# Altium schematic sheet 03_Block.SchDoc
size 459 x 350 mm
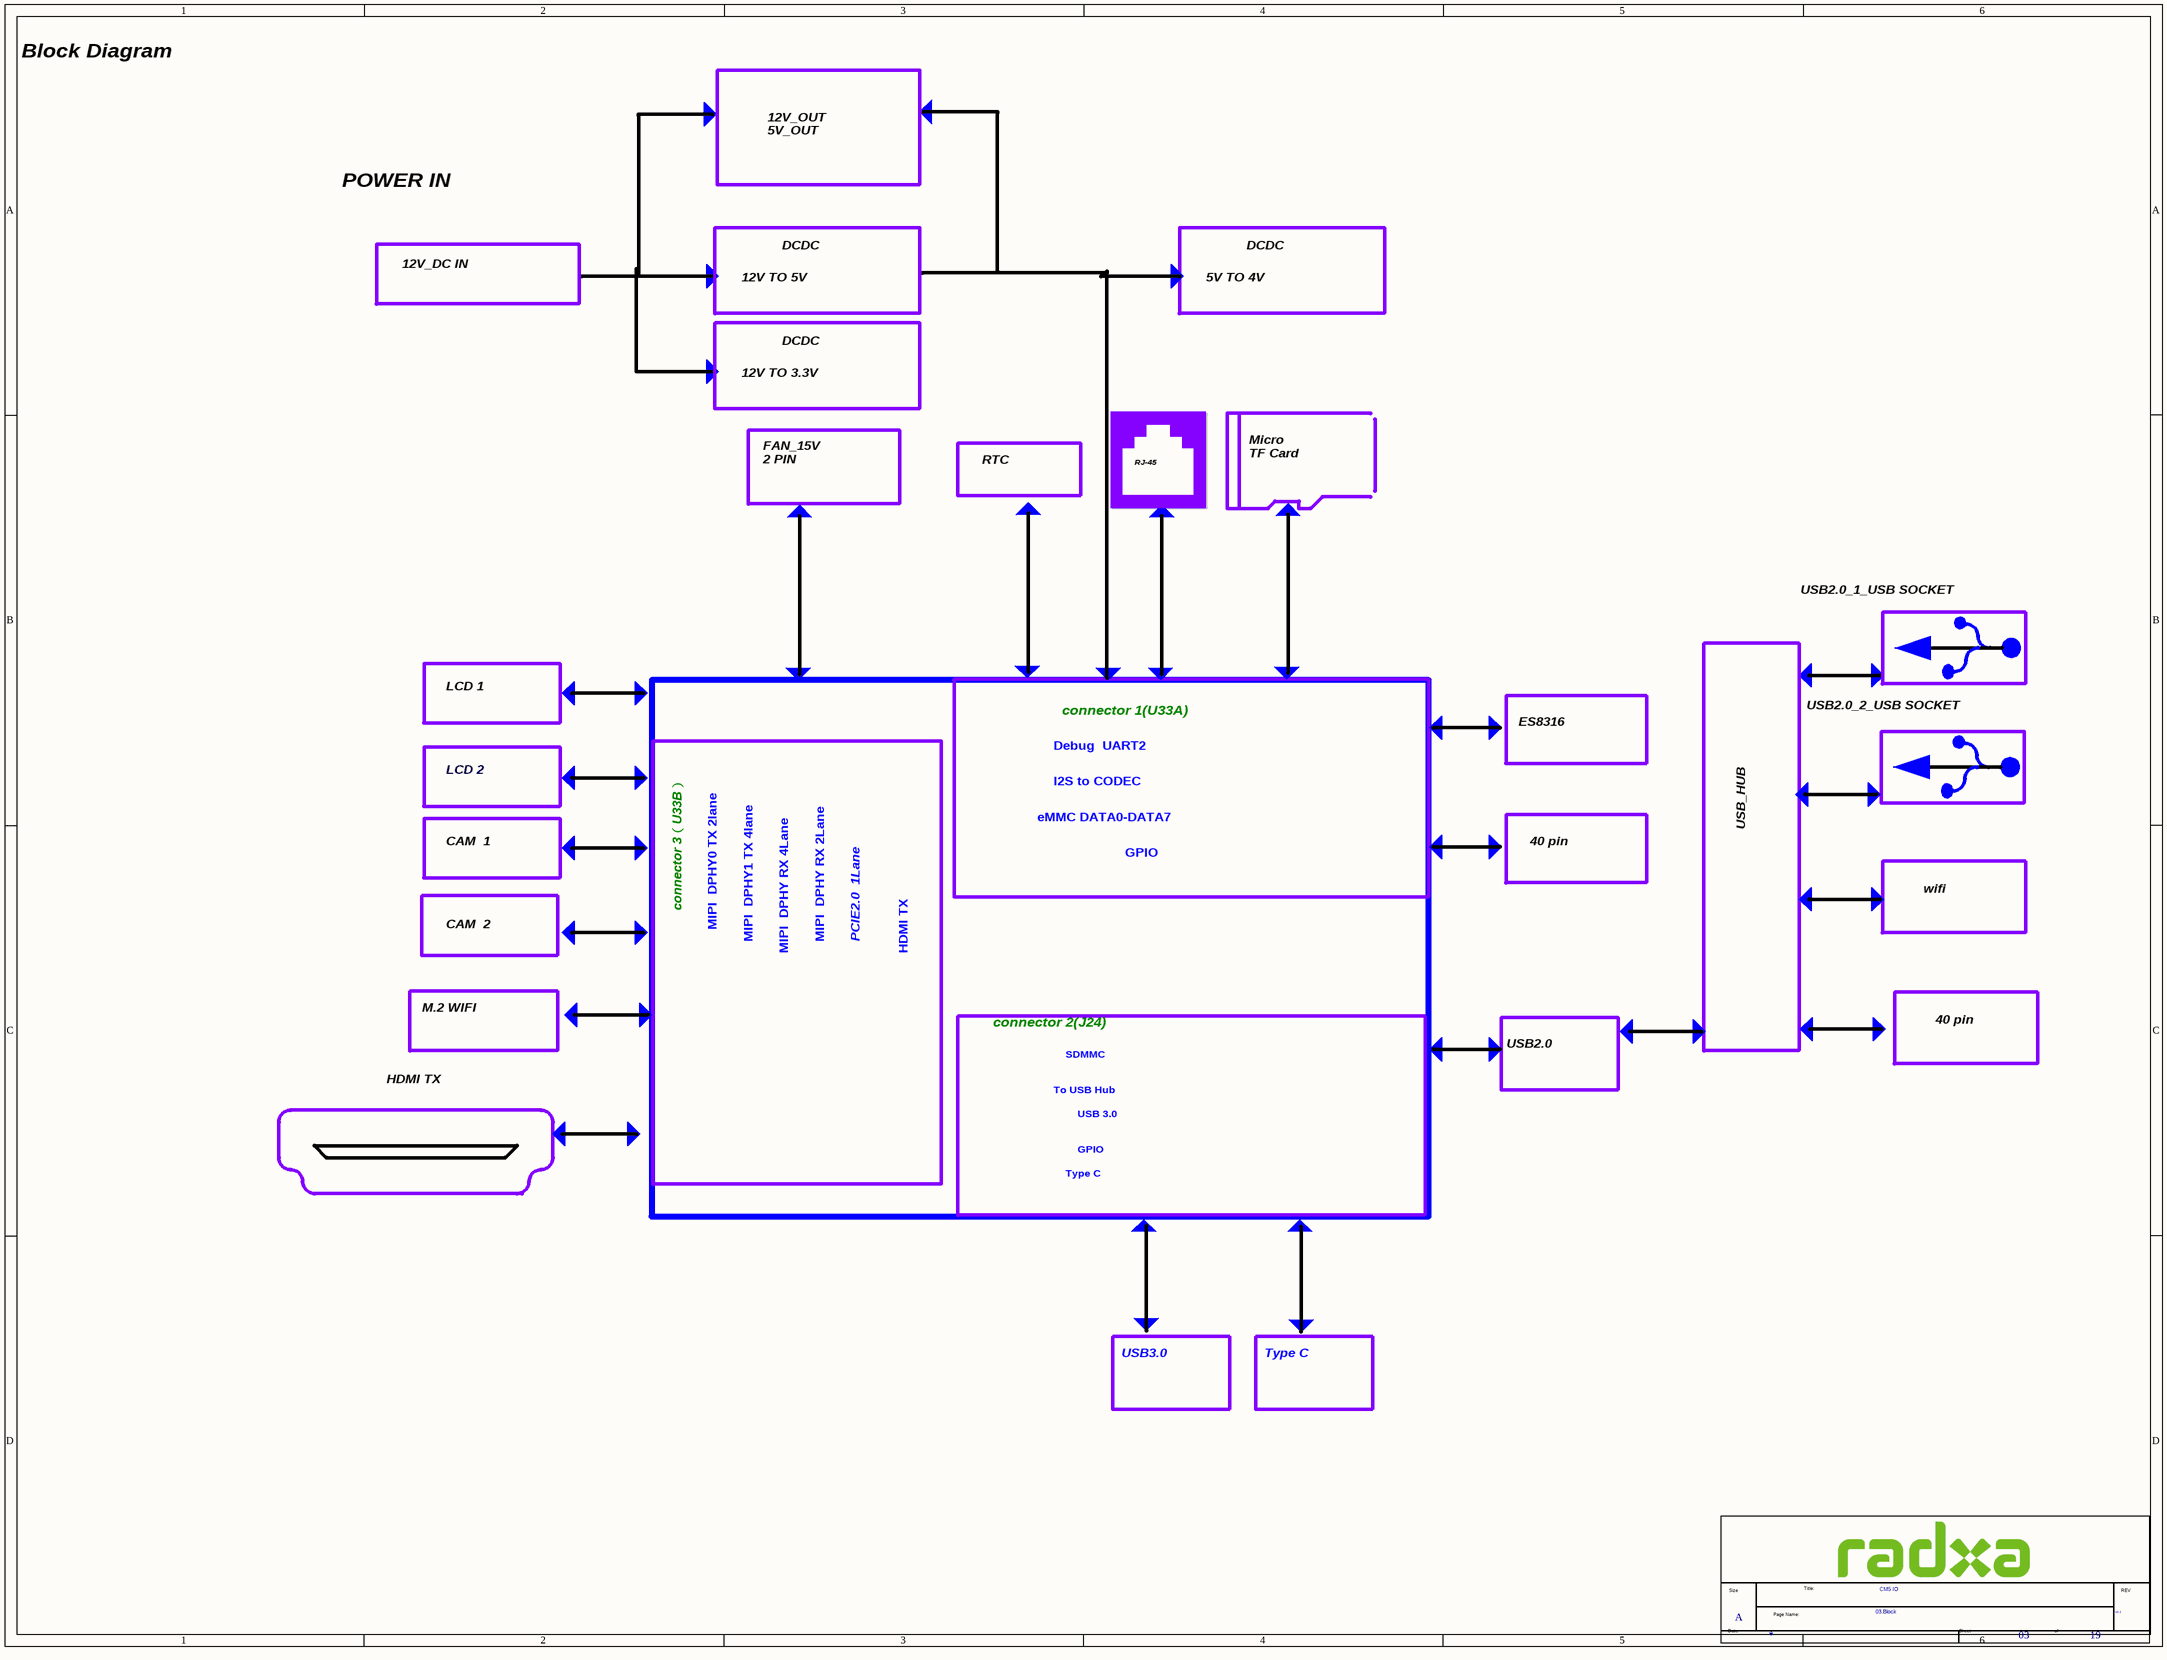
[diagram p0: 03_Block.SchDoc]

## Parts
*  Doc: 03.Block  RevCode: V2.2  Title: CM5 IO  Page Size: A  Page Number: 03  Page Count: 19  (hidden comment: radxa_1010)  (graphical)

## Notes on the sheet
- Block Diagram
- 12V_OUT
  5V_OUT
- POWER IN
- 12V_DC IN
- 12V TO 5V
- DCDC
- 5V TO 4V
- 12V TO 3.3V
- FAN_15V
  2 PIN
- RTC
- RJ-45
- Micro
  TF Card
- USB2.0_1_USB SOCKET
- LCD 1
- connector 1(U33A)
- USB2.0_2_USB SOCKET
- LCD 2
- Debug  UART2
- ES8316
- eMMC DATA0-DATA7
- I2S to CODEC
- USB_HUB
- CAM  1
- GPIO
- 40 pin
- wifi
- CAM  2
- connector 3（U33B）
- MIPI  DPHY0 TX 2lane
- MIPI  DPHY1 TX 4lane
- MIPI  DPHY RX 4Lane
- MIPI  DPHY RX 2Lane
- PCIE2.0  1Lane
- HDMI TX
- M.2 WIFI
- connector 2(J24)
- SDMMC
- USB2.0
- To USB Hub
- USB 3.0
- Type C
- USB3.0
